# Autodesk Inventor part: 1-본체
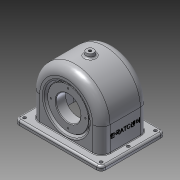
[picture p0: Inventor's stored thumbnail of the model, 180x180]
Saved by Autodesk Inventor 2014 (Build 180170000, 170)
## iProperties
Created: 2015-09
Part Number: 1-본체
Material: 알루미늄 6061
Document SubType Name: Modeling
Designer: Administrator
Density: 2.71 g/cm^3
Appearance: 알루미늄 - 평지
Mass: 676.042 g
Surface Area: 897.785 cm^2
Volume: 249.462 cm^3
Author: Administrator
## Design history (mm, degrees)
sketch "스케치1"
  geometry: L1 (57, 0)-(57, -47); L2 (-57, 0)-(-57, -47); L3 (-57, -47)-(57, -47); A1 r 57 centre (0, 0) between (32.249, -47) and (-32.249, -47); 1 further point
  constraints: 6 end point, 4 point on circle, 2 point on line, 2 tangent, 1 centre point, 1 coincident, 1 perpendicular, 1 vertical
  dimensions: "d1" = 57 radius of A1; "d2" = 47 distance from line of point (0, 0) L3; "d3" = 114 distance of L2.end L1.end
extrude "돌출1" new body sketch "스케치1" stored distance "d4" = 77; taper "d5" = 0 deg
sketch "스케치3"
  geometry: L1 (127, 13.5)-(-13, 13.5); L2 (-13, 13.5)-(-13, -90.5); L3 (-13, -90.5)-(127, -90.5); L4 (127, -90.5)-(127, 13.5); L5 (114, 0)-(0, 0) reference; L6 (114, 0)-(114, -77) reference; 4 further points
  constraints: 8 end point, 3 midpoint, 2 parallel, 1 horizontal, 1 horizontal alignment, 1 perpendicular, 1 vertical alignment
  dimensions: "d8" = 104 distance of L3.end L1.start; "d9" = 140 distance of L1.start L1.end
extrude "돌출2" join sketch "스케치3" distance "d11" = 7; taper "d12" = 0 deg
fillet "모깎기1" dims "d13" = 14
fillet "모깎기2" dims "d14" = 7
sketch "스케치5"
  geometry: L1 (57, -40)-(57, 0) reference; L2 (-57, 0)-(-57, -40) reference; L3 (-51, -47)-(-51, 0); L4 (51, 0)-(51, -47); L5 (63, -47)-(-63, -47) reference; A1 r 57 centre (0, 0) between (57, 0) and (-57, 0) reference; A2 r 51 centre (0, 0) between (51, 0) and (-51, 0); 1 further point
  constraints: 4 end point, 2 point on circle, 2 point on line, 1 centre point, 2 other
  dimensions: "d16" = 6 radial gap between concentric circles of A1 A2
extrude "돌출3" cut sketch "스케치5" stored distance "d17" = 67; taper "d18" = 0 deg
fillet "모깎기3" dims "d19" = 9
node "작업 평면1"
sketch "스케치6"
  geometry: C1 r 6 at (63, 52); 1 further point
  constraints: 1 centre point, 1 coincident
  dimensions: "d21" = 12 diameter of C1
extrude "돌출4" join sketch "스케치6" stored distance "d22" = 67; taper "d23" = 10 deg
sketch "스케치7"
  geometry: L1 (-33.5, 39.747)-(-19.5, 28); L2 (-19.5, 28)-(-19.5, 0); L3 (-33.5, 39.747)-(-33.5, 0); L4 (-33.5, 42)-(-33.5, 0) reference; L5 (24.5, 0)-(-24.5, 0) reference; L6 (-38.5, 0)-(-38.5, 43) reference; L7 (-19.5, 0)-(-33.5, 0); 1 further point
  constraints: 8 end point, 3 point on line, 1 collinear, 1 parallel, 1 vertical
  dimensions: "d24" = 28 distance from line of L5 L1.end; "d25" = 50 deg angle of L1 L2; "d26" = 19 distance between parallel lines of L2 L6
revolve "회전1" sketch "스케치7" stored, may be unused: angle "d27" = 90 deg
sketch "스케치8"
  geometry: C1 r 31 at (0, 0); 1 further point
  constraints: 1 centre point, 1 coincident
  dimensions: "d29" = 62 diameter of C1
extrude "돌출5" join sketch "스케치8" distance "d30" = 10; taper "d31" = 0 deg
sketch "스케치9"
  geometry: L1 (-38.5, 37.416)-(-33.237, 33); L2 (-33.237, 33)-(-35.5, 33); L3 (-35.5, 33)-(-35.5, 0); L4 (-38.5, 37.416)-(-38.5, 0); L5 (-38.5, 0)-(-35.5, 0); L6 (-33.5, 39.747)-(-19.5, 28) reference; 2 further points
  constraints: 10 end point, 2 parallel, 2 perpendicular, 1 coincident, 1 horizontal
  dimensions: "d32" = 3 distance between parallel lines of L3 L4; "d33" = 33 distance from line of point (0, 0) L2; "d34" = 5 distance between parallel lines of L6 L1
revolve "회전2" sketch "스케치9" stored, may be unused: angle "d35" = 90 deg
hole "구멍1" diameter "d38" = 40; stored, may be unused: countersink angle "d42" = 90 deg, drill point angle "d44" = 118 deg; dims "d36" = 10, "d37" = 10, "d39" = 6, "d40" = 4, "d41" = 2, "d43" = 8
chamfer "모따기1" distance "d45" = 1; stored, may be unused: second distance "d46" = 2, angle "d47" = 45 deg
fillet "모깎기4" dims "d48" = 1
hole "구멍2" diameter "d51" = 4.459; stored, may be unused: countersink angle "d55" = 90 deg, drill point angle "d57" = 118 deg; dims "d52" = 50, "d53" = 4, "d54" = 2, "d56" = 8, "d58" = 10, "d59" = 10
fillet "모깎기5" dims "d60" = 3
sketch "스케치10"
  geometry: L1 (0, 0)-(0, -24)
  constraints: 2 end point, 1 vertical
  dimensions: "d61" = 24 distance of L1.start L1.end
hole "구멍3" sketch "스케치10" at (0, -24) diameter "d62" = 2.459; stored, may be unused: countersink angle "d66" = 90 deg, drill point angle "d68" = 118 deg; dims "d63" = 6, "d64" = 4, "d65" = 2, "d67" = 8
sketch "스케치11"
  geometry: L1 (0, 0)-(0, 28)
  constraints: 2 end point, 1 vertical
  dimensions: "d72" = 28 distance of L1.start L1.end
hole "구멍4" sketch "스케치11" at (0, 28) diameter "d73" = 2.459; stored, may be unused: countersink angle "d77" = 90 deg, drill point angle "d79" = 118 deg; dims "d74" = 7, "d75" = 4, "d76" = 2, "d78" = 9
fillet "모깎기6" dims "d83" = 0.5
fillet "모깎기7" dims "d84" = 3
sketch "스케치12"
  geometry: L1 (-119, -82.5)-(5, -82.5); L2 (5, -82.5)-(5, 5.5); L3 (5, 5.5)-(-119, 5.5); L4 (-119, 5.5)-(-119, -82.5); L5 (-127, -83.5)-(-127, 6.5) reference; L6 (-120, -90.5)-(6, -90.5) reference; 3 further points
  constraints: 8 end point, 2 midpoint, 2 parallel, 1 horizontal, 1 horizontal alignment, 1 perpendicular, 1 vertical alignment
  dimensions: "d102" = 8 distance between parallel lines of L5 L4; "d103" = 8 distance between parallel lines of L6 L1
sketch "스케치13"
  geometry: L1 (6.276, -0.387)-(6.276, 49.387); L2 (6.276, 49.387)-(27.724, 49.387); L3 (27.724, 49.387)-(27.724, -0.387); L4 (27.724, -0.387)-(6.276, -0.387); L5 (47, 69.5)-(47, -20.5) reference; L6 (0, -14)-(39, -14) reference; 3 further points
  constraints: 2 midpoint, 2 other
  dimensions: "d98" = 30 distance from line of L5 point (17, -0.387); "d99" = 38.5 distance from line of L6 point (6.276, 24.5)
feature "엠보싱1" sketch "스케치13" dims "d1" = 57, "d2" = 47, "d3" = 114, "d100" = 0.5, "d101" = 0
hole "구멍6" sketch "스케치12" diameter "d104" = 5; stored, may be unused: countersink angle "d108" = 90 deg, drill point angle "d110" = 118 deg; dims "d105" = 6, "d106" = 4, "d107" = 2, "d109" = 8
node "솔리드1"
pattern_circular "원형 패턴1" dims angle "d70" = 360 deg
pattern_circular "원형 패턴2" dims angle "d81" = 360 deg
pattern_linear "직사각형 패턴2" dims "d113" = 44, "d116" = 124
